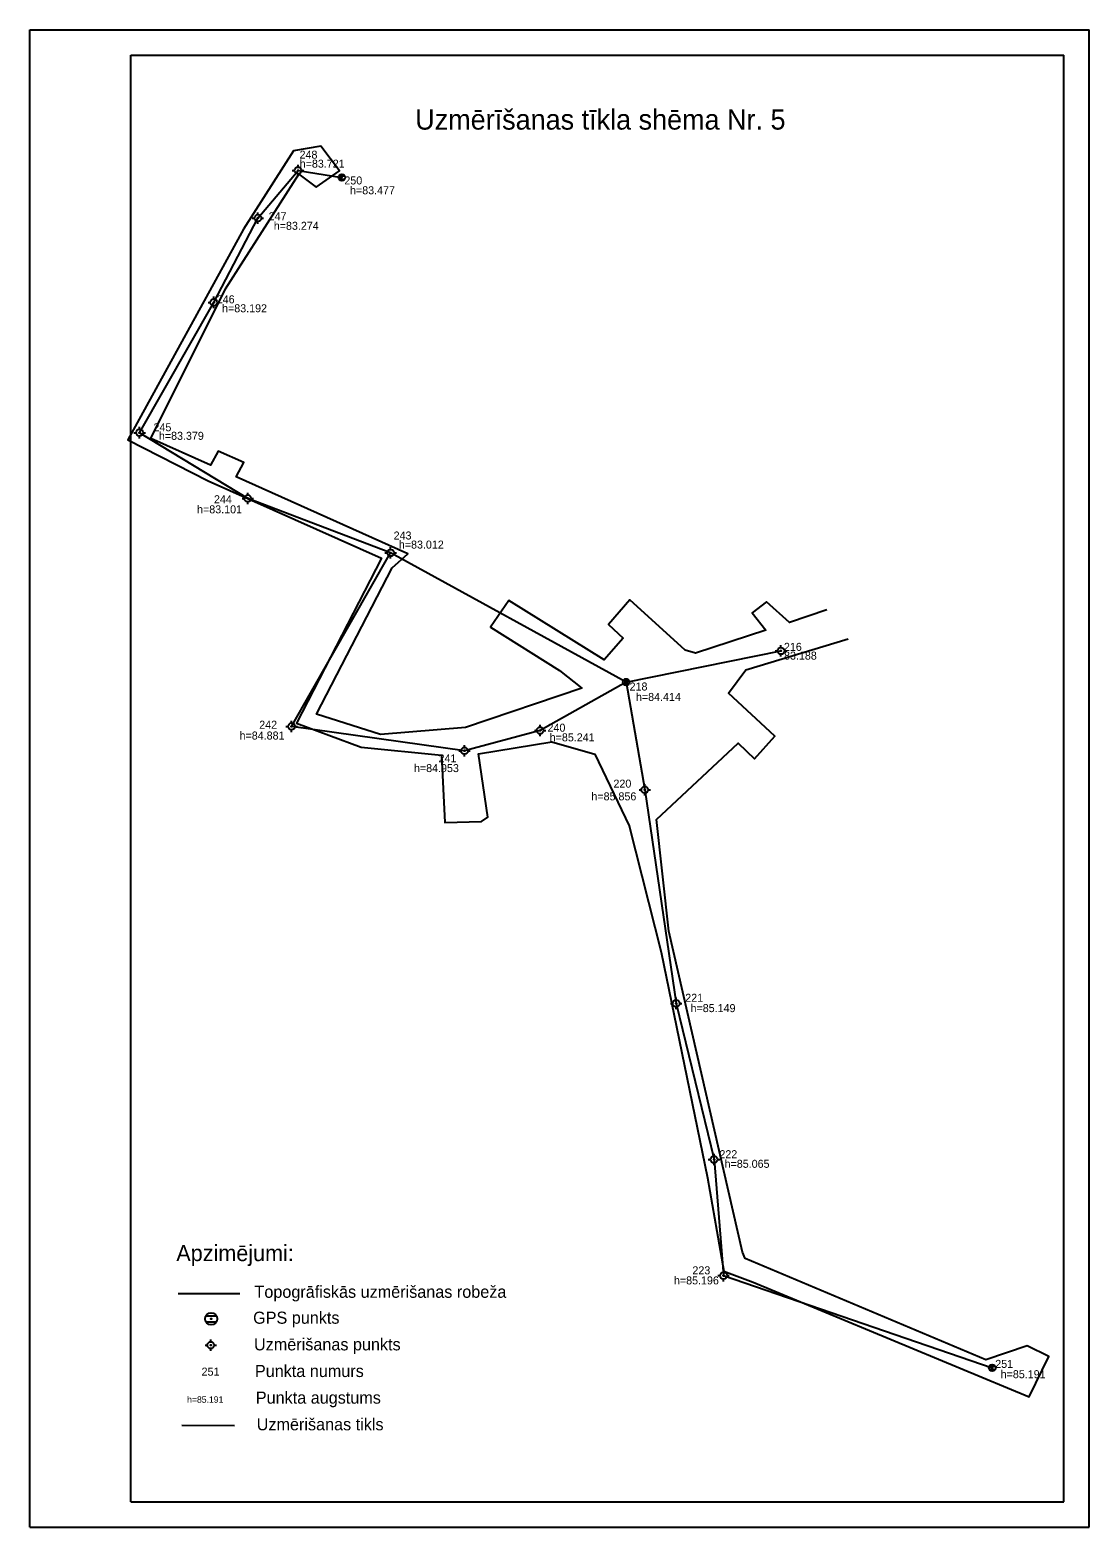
# Model space of a CAD drawing. Extents: x 614854 to 615516, y 262034 to 262969.
import ezdxf

# ---------------------------------------------------------------- set-up
doc = ezdxf.new("R2010")
doc.units = 0
for name, color, linetype in [('Level 19', 7, 'Continuous'), ('Level 25', 7, 'Continuous'), ('Level 63', 7, 'Continuous')]:
    doc.layers.add(name, color=color, linetype=linetype)

msp = doc.modelspace()

# ---------------------------------------------------------------- linework, layer by layer
at = {"layer": 'Level 19'}
for p, q in [((614996.66, 262851.59), (615021.77, 262881.37)), ((615018.17, 262881.37), (615019.61, 262881.37)), ((615021.77, 262883.53), (615021.77, 262884.97)), ((615021.77, 262881.37), (615049.08, 262876.96)), ((615023.93, 262881.37), (615025.37, 262881.37)), ((615021.77, 262877.77), (615021.77, 262879.21)), ((615047.26, 262878.01), (615050.9, 262878.01)), ((615047.26, 262875.91), (615050.9, 262875.91)), ((614996.66, 262853.75), (614996.66, 262855.19)), ((614969.13, 262798.92), (614996.66, 262851.59)), ((614993.06, 262851.59), (614994.5, 262851.59)), ((614996.66, 262847.99), (614996.66, 262849.43)), ((614998.82, 262851.59), (615000.26, 262851.59)), ((614922.78, 262717.49), (614969.13, 262798.92)), ((614965.53, 262798.92), (614966.97, 262798.92)), ((614969.13, 262801.08), (614969.13, 262802.52)), ((614969.13, 262795.32), (614969.13, 262796.76)), ((614971.29, 262798.92), (614972.73, 262798.92)), ((614919.18, 262717.49), (614920.62, 262717.49)), ((614922.78, 262719.65), (614922.78, 262721.09)), ((614990.38, 262676.41), (614922.78, 262717.49)), ((614922.78, 262713.89), (614922.78, 262715.33)), ((614924.94, 262717.49), (614926.38, 262717.49)), ((614986.78, 262676.41), (614988.22, 262676.41)), ((614990.38, 262678.57), (614990.38, 262680.01)), ((615079.61, 262642.41), (614990.38, 262676.41)), ((614992.54, 262676.41), (614993.98, 262676.41)), ((614990.38, 262672.82), (614990.38, 262674.26)), ((615017.73, 262533.93), (615079.61, 262642.41)), ((615076.01, 262642.41), (615077.45, 262642.41)), ((615079.61, 262644.57), (615079.61, 262646.01)), ((615226.71, 262561.65), (615079.61, 262642.41)), ((615079.61, 262638.81), (615079.61, 262640.25)), ((615081.77, 262642.41), (615083.21, 262642.41)), ((615226.71, 262561.65), (615323.38, 262581.17)), ((615319.78, 262581.17), (615321.22, 262581.17)), ((615323.38, 262583.33), (615323.38, 262584.77)), ((615325.54, 262581.17), (615326.98, 262581.17)), ((615323.38, 262577.57), (615323.38, 262579.01)), ((615224.9, 262562.7), (615228.53, 262562.7)), ((615226.71, 262561.65), (615172.97, 262531.41)), ((615224.9, 262560.6), (615228.53, 262560.6)), ((615226.71, 262561.65), (615238.34, 262494.35)), ((615017.73, 262536.09), (615017.73, 262537.53)), ((615172.97, 262533.57), (615172.97, 262535.01)), ((615014.13, 262533.93), (615015.57, 262533.93)), ((615125.72, 262518.72), (615017.73, 262533.93)), ((615017.73, 262530.33), (615017.73, 262531.77)), ((615019.89, 262533.93), (615021.33, 262533.93)), ((615172.97, 262531.41), (615125.72, 262518.72)), ((615169.37, 262531.41), (615170.81, 262531.41)), ((615172.97, 262527.81), (615172.97, 262529.25)), ((615175.13, 262531.41), (615176.57, 262531.41)), ((615122.12, 262518.72), (615123.56, 262518.72)), ((615125.72, 262520.88), (615125.72, 262522.32)), ((615125.72, 262515.12), (615125.72, 262516.57)), ((615127.88, 262518.72), (615129.32, 262518.72)), ((615238.34, 262496.51), (615238.34, 262497.95)), ((615234.74, 262494.35), (615236.18, 262494.35)), ((615238.34, 262494.35), (615257.93, 262360.86)), ((615238.34, 262490.75), (615238.34, 262492.19)), ((615240.5, 262494.35), (615241.94, 262494.35)), ((615254.33, 262360.86), (615255.77, 262360.86)), ((615257.93, 262363.03), (615257.93, 262364.47)), ((615257.93, 262360.86), (615281.6, 262263.32)), ((615257.93, 262357.27), (615257.93, 262358.71)), ((615260.09, 262360.86), (615261.53, 262360.86)), ((615278, 262263.32), (615279.44, 262263.32)), ((615281.6, 262265.48), (615281.6, 262266.92)), ((615281.6, 262263.32), (615287.53, 262190.78)), ((615283.76, 262263.32), (615285.2, 262263.32)), ((615281.6, 262259.72), (615281.6, 262261.16)), ((615283.93, 262190.78), (615285.37, 262190.78)), ((615287.53, 262192.94), (615287.53, 262194.38)), ((615287.53, 262190.78), (615455.36, 262133.1)), ((615287.53, 262187.18), (615287.53, 262188.62)), ((615289.69, 262190.78), (615291.13, 262190.78)), ((614964.22, 262165.65), (614970.77, 262165.65)), ((614964.22, 262161.87), (614970.77, 262161.87)), ((614967.27, 262149.45), (614967.27, 262150.89)), ((614963.67, 262147.29), (614965.11, 262147.29)), ((614967.27, 262143.69), (614967.27, 262145.13)), ((614969.43, 262147.29), (614970.87, 262147.29)), ((615453.55, 262134.15), (615457.18, 262134.15)), ((615453.55, 262132.05), (615457.18, 262132.05)), ((614982, 262096.94), (614949.27, 262097.01))]:
    msp.add_line(p, q, dxfattribs=at)
for centre, radius in [((615021.77, 262881.37), 2.16), ((615021.77, 262881.37), 0.288), ((615049.08, 262876.96), 2.1), ((615049.08, 262876.96), 0.112), ((614996.66, 262851.59), 2.16), ((614996.66, 262851.59), 0.288), ((614969.13, 262798.92), 2.16), ((614969.13, 262798.92), 0.288), ((614922.78, 262717.49), 2.16), ((614922.78, 262717.49), 0.288), ((614990.38, 262676.41), 2.16), ((614990.38, 262676.41), 0.288), ((615079.61, 262642.41), 2.16), ((615079.61, 262642.41), 0.288), ((615323.38, 262581.17), 2.16), ((615323.38, 262581.17), 0.288), ((615226.71, 262561.65), 2.1), ((615226.71, 262561.65), 0.112), ((615017.73, 262533.93), 2.16), ((615017.73, 262533.93), 0.288), ((615172.97, 262531.41), 2.16), ((615172.97, 262531.41), 0.288), ((615125.72, 262518.72), 2.16), ((615125.72, 262518.72), 0.288), ((615238.34, 262494.35), 2.16), ((615238.34, 262494.35), 0.288), ((615257.93, 262360.86), 2.16), ((615257.93, 262360.86), 0.288), ((615281.6, 262263.32), 2.16), ((615281.6, 262263.32), 0.288), ((615287.53, 262190.78), 2.16), ((615287.53, 262190.78), 0.288), ((614967.5, 262163.76), 3.78), ((614967.5, 262163.76), 0.202), ((614967.27, 262147.29), 2.16), ((614967.27, 262147.29), 0.288), ((615455.36, 262133.1), 2.1), ((615455.36, 262133.1), 0.112)]:
    msp.add_circle(centre, radius, dxfattribs=at)
at = {"layer": 'Level 25'}
msp.add_line((614946.98, 262179.58), (614985.49, 262179.58), dxfattribs=at)
msp.add_lwpolyline([(615351.95, 262606.88), (615340.38, 262602.82), (615328.73, 262598.99), (615314.4, 262611.83), (615305.45, 262604.88), (615313.93, 262594.13), (615269.96, 262579.68), (615263.54, 262581.66), (615228.9, 262613.11), (615215.62, 262597.59), (615224.92, 262589.16), (615213.01, 262575.53), (615153.37, 262612.63), (615141.96, 262595.95), (615185, 262568.93), (615199.04, 262557.91), (615126.33, 262533.25), (615073.33, 262528.98), (615033.35, 262541.69), (615080.59, 262633.11), (615090.25, 262641.72), (614983.1, 262689.95), (614987.95, 262698.96), (614971.93, 262706.04), (614967.17, 262697.13), (614929.81, 262713.94), (614976.39, 262807.36), (615022.29, 262878.97), (615033.02, 262870.83), (615047.61, 262881.12), (615036.02, 262896.56), (615018.86, 262893.55), (614987.68, 262844.67), (614915.49, 262713.06), (614965.53, 262687.34), (615073.83, 262639.15), (615020.77, 262535.9), (615061.09, 262521.05), (615111.27, 262515.95), (615113.37, 262473.98), (615136.25, 262474.51), (615140.2, 262477.14), (615134.54, 262516.79), (615180.26, 262524.33), (615207.23, 262516.56), (615228.67, 262471.8), (615228.67, 262471.8), (615248.52, 262392.88), (615277.51, 262251.8), (615287.71, 262193.47), (615306, 262186.62), (615478.35, 262115.07), (615490.66, 262140.13), (615477.25, 262146.97), (615451.38, 262138.15), (615301.11, 262201.55), (615299.27, 262205.46), (615253.34, 262405.97), (615245.71, 262475.78), (615296.57, 262523.4), (615306.96, 262513.78), (615319.66, 262527.88), (615290.57, 262554.64), (615301.53, 262569.35), (615365.42, 262588.75)], dxfattribs=at)
at = {"layer": 'Level 63'}
for p, q in [((614854.31, 262033.63), (614854.31, 262969.18)), ((614854.31, 262969.18), (615515.81, 262969.18)), ((615515.81, 262033.63), (615515.81, 262969.18)), ((614917.31, 262049.38), (614917.31, 262953.43)), ((614917.31, 262953.43), (615500.06, 262953.43)), ((615500.06, 262049.38), (615500.06, 262953.43)), ((614917.31, 262049.38), (615500.06, 262049.38)), ((614854.31, 262033.63), (615515.81, 262033.63))]:
    msp.add_line(p, q, dxfattribs=at)

# ---------------------------------------------------------------- texts
at = {"layer": 'Level 19'}
for s, height, p in [(' 248', 5, (615020.85, 262888.74)), (' h=83.721', 5, (615020.94, 262883.12)), (' 250', 5, (615048.84, 262872.63)), ('h=83.477', 5, (615054.22, 262866.49)), (' 247', 5, (615001.52, 262850.25)), ('h=83.274', 5, (615006.61, 262844.3)), (' 246', 5, (614969.13, 262798.35)), ('h=83.192', 5, (614974.3, 262792.75)), (' 245', 5, (614929.63, 262718.39)), ('h=83.379', 5, (614934.83, 262713.06)), (' 244', 5, (614967.38, 262673.41)), ('h=83.101', 5, (614958.69, 262667.11)), (' 243', 5, (615079.61, 262650.75)), ('h=83.012', 5, (615084.71, 262645.08)), (' 216', 5, (615323.38, 262581.17)), (' 83.188', 5, (615323.46, 262575.7)), (' 218', 5, (615226.98, 262556.39)), ('h=84.414', 5, (615232.8, 262549.88)), (' 242', 5, (614995.65, 262532.51)), (' 240', 5, (615175.72, 262530.66)), ('h=84.881', 5, (614985.23, 262525.76)), ('h=85.241', 5, (615178.93, 262524.61)), (' 241', 5, (615107.66, 262511.53)), ('h=84.953', 5, (615094.15, 262505.41)), (' 220', 5, (615216.91, 262495.7)), ('h=85.856', 5, (615204.98, 262487.74)), (' 221', 5, (615261.74, 262361.87)), ('h=85.149', 5, (615266.91, 262355.42)), (' 222', 5, (615283.08, 262264.13)), ('h=85.065', 5, (615288.18, 262258.14)), ('h=85.196', 5, (615256.53, 262185.27)), (' 223', 5, (615266.22, 262191.56)), ('251', 5.04, (614961.47, 262128.22)), (' 251', 5, (615455.36, 262133.1)), ('h=85.191', 5, (615460.6, 262126.66)), (' h=85.191', 4.032, (614950.98, 262111.29))]:
    msp.add_text(s, height=height, dxfattribs=at).set_placement(p)
at = {"layer": 'Level 63'}
for s, height, p in [('Uzmērīšanas tīkla shēma Nr. 5', 12.6, (615094.95, 262906.9)), ('Apzimējumi:', 10.08, (614945.73, 262199.81)), ('Topogrāfiskās uzmērišanas robeža', 7.56, (614994.54, 262176.89)), ('GPS punkts', 7.56, (614993.69, 262160.68)), ('Uzmērišanas punkts', 7.56, (614994.26, 262144.03)), ('Punkta numurs', 7.56, (614994.82, 262127.38)), ('Punkta augstums', 7.56, (614995.39, 262110.73)), ('Uzmērišanas tikls', 7.56, (614995.95, 262094.08))]:
    msp.add_text(s, height=height, dxfattribs=at).set_placement(p)

doc.saveas('drawing.dxf')
